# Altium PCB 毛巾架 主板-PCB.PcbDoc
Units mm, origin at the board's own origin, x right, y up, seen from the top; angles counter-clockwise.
Board outline 72 x 43 mm, 2 copper layers (Top Layer, Bottom Layer); 69 components, 52 nets, 212 pads, 98 vias.
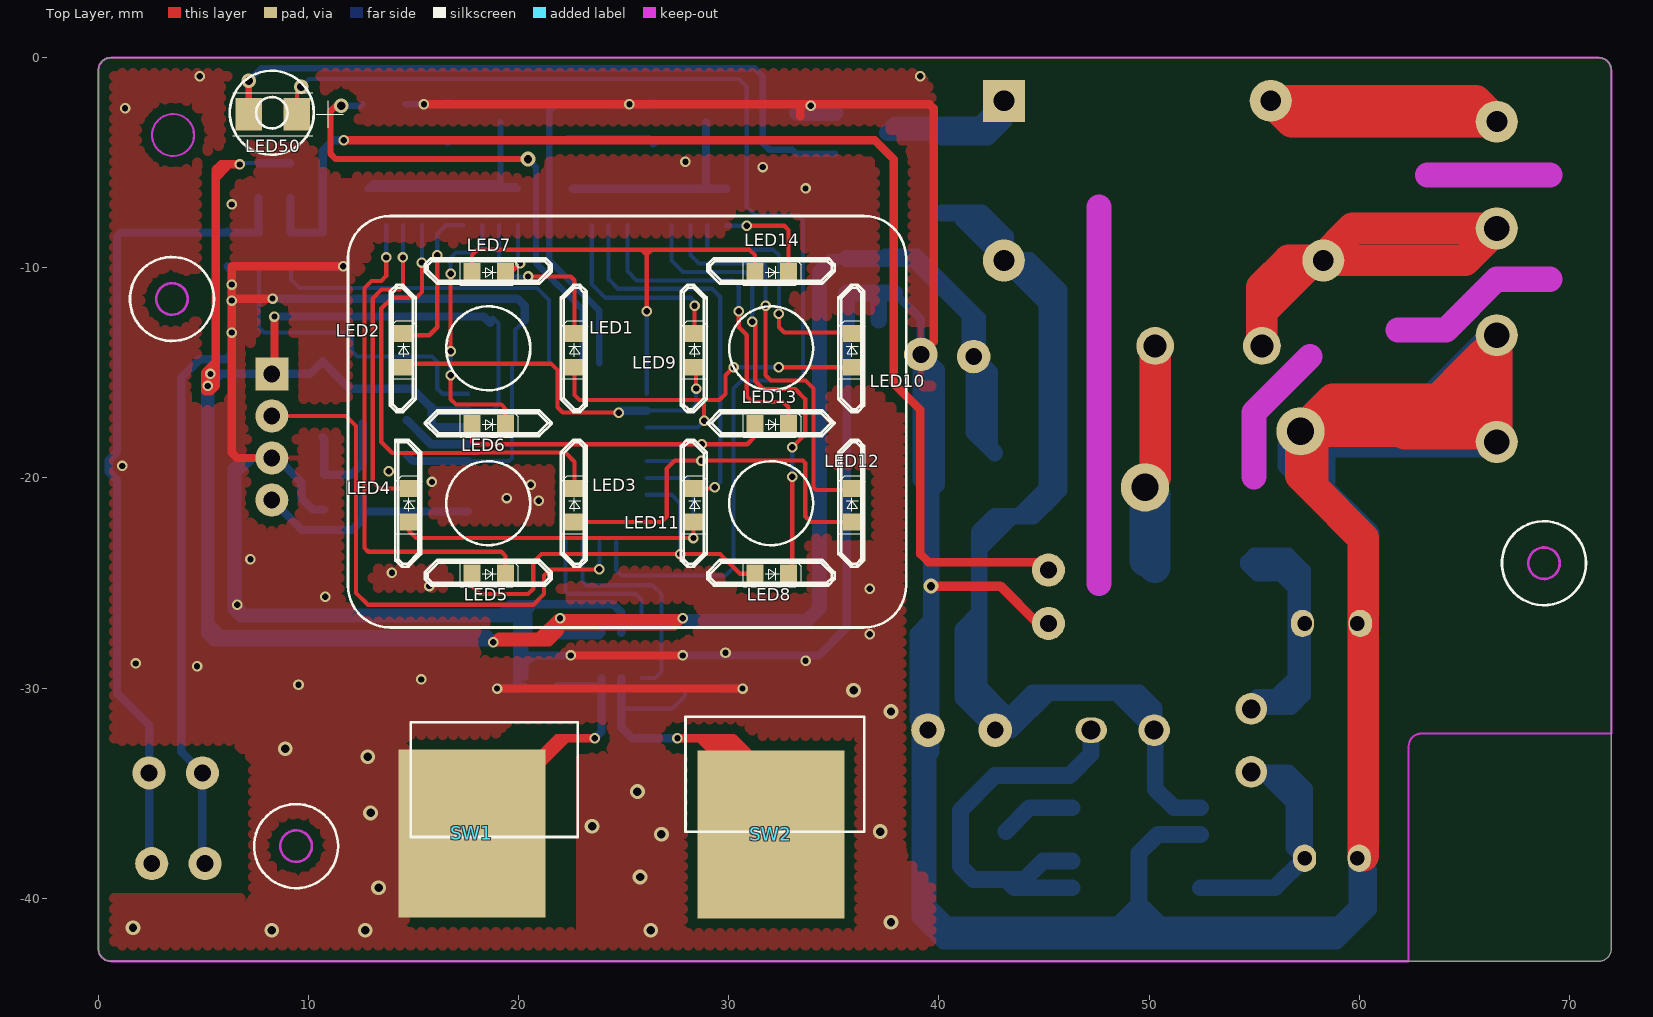
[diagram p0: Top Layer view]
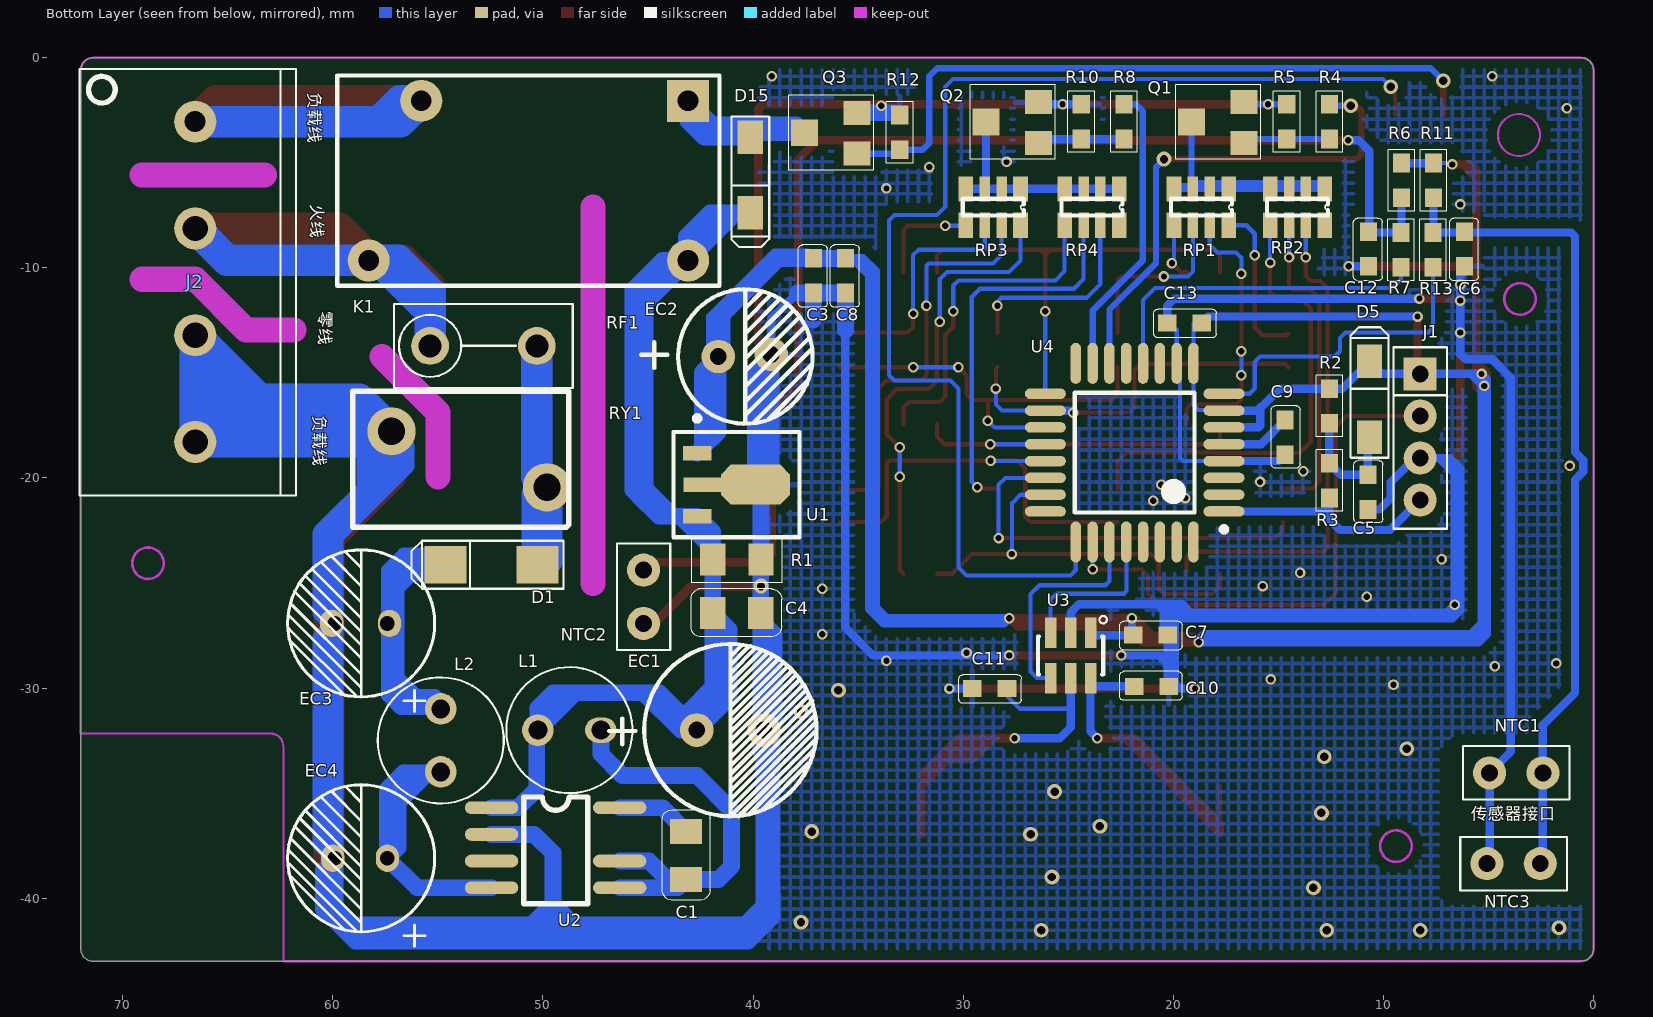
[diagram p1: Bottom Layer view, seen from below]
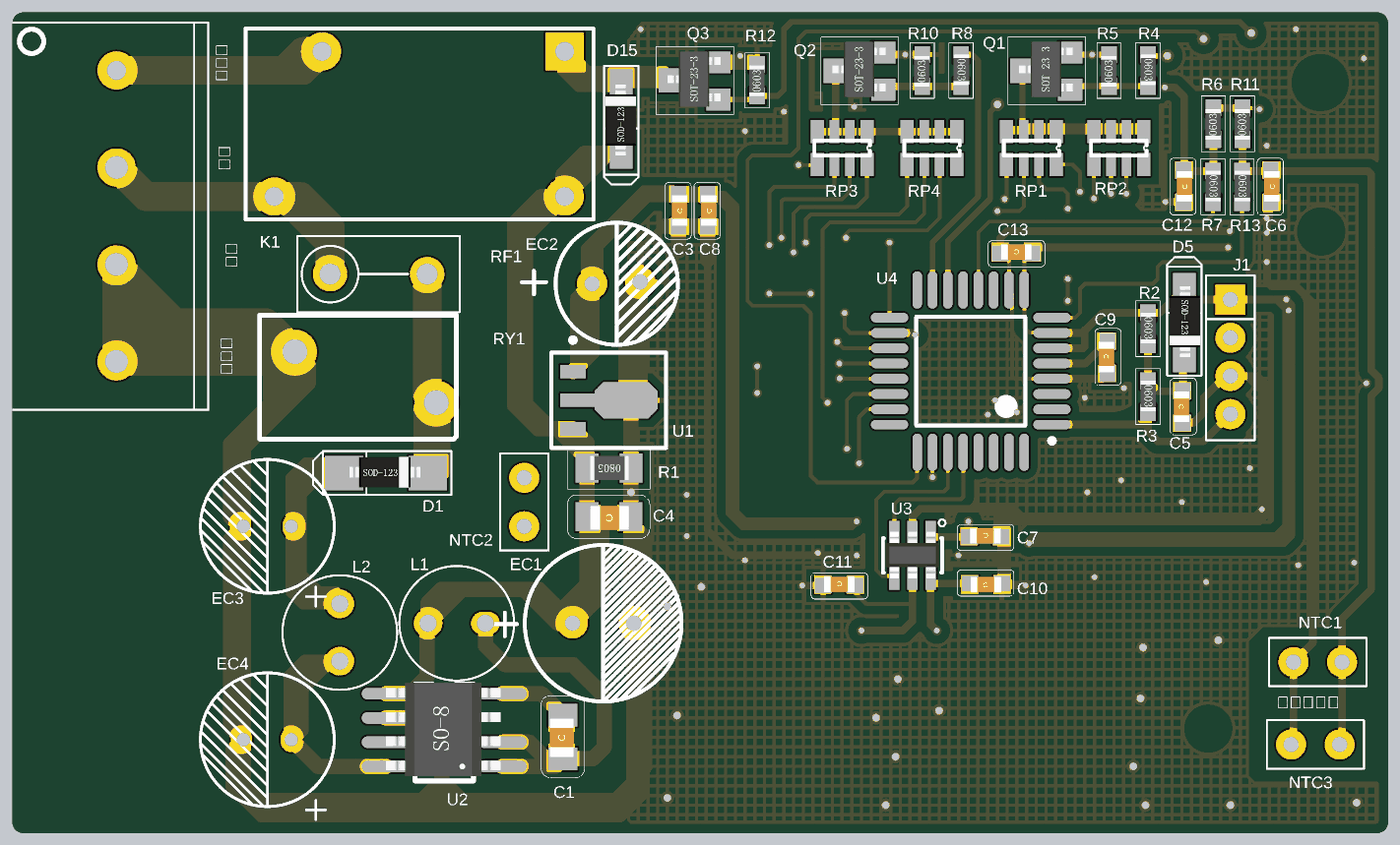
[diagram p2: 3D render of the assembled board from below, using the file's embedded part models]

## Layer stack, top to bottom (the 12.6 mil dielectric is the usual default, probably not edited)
Top Layer: signal copper 0.0356
Dielectric: dielectric 0.32, FR-4, Dk 4.8
Bottom Layer: signal copper 0.0356

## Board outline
0,-42.4 0,-0.6 cw(c0.6,-0.6) 0.6,0 71.4,0 cw(c71.4,-0.6) 72,-0.6 72,-42.4 cw(c71.4,-42.4) 71.4,-43 0.6,-43 cw(c0.6,-42.4)

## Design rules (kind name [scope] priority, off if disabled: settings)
Clearance Clearance_1 [InPolygon] p1: gap=0.45
Clearance [All] p2: gap=0.2
HoleSize [All] p1 off: absolutevalues=TRUE maxlimit=2.54 minlimit=0.025 maxpercent=80.000 minpercent=20.000
HoleToHoleClearance [All] p1 off: gap=0.254 allowstackedmicrovias=TRUE
LayerPairs [All] p1 off: enforce=TRUE
MinimumSolderMaskSliver [All] p1 off: minsoldermaskwidth=0.254
NetAntennae [All] p1 off: netantennaetolerance=0
PolygonConnect PolygonConnect_1 [IsVia] p1: connectstyle=Direct reliefconductorwidth=0.254 reliefentries=4 polygonreliefangle="90 Angle"
PolygonConnect [All] p2: connectstyle=Relief reliefconductorwidth=0.254 reliefentries=4 polygonreliefangle="90 Angle"
RoutingVias [All] p1: holewidth=0.711 width=1.27 viastyle="Through Hole" minholewidth=0.711 minwidth=1.27 maxholewidth=0.711 maxwidth=1.27
SilkToSilkClearance [All] p1 off: silktosilkclearance=0.254
SilkscreenOverComponentPads [All] p1 off: minsilkscreentomaskgap=0.254
SolderMaskExpansion [All] p1: expansion=0.102
Width [All] p1: maxlimit=1.5 minlimit=0.17 preferedwidth=0.4
21 further rules are at their usual default settings.

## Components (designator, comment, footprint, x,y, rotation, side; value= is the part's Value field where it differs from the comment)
C1 "1uF/0805" CAP/SMT/0805C 43.18,-39.116 r90 bottom
C3 "0.1uF/0603" CAP/SMT/0603C 37.084,-11.176 r90 bottom
C4 "1uF/0805" CAP/SMT/0805C 39.624,-26.416 r0 bottom
C5 "0.1uF/0603" CAP/SMT/0603C 10.795,-19.876 r270 bottom
C6 "0.1uF/0603" CAP/SMT/0603C 6.096,-9.906 r90 bottom
C7 "1uF/0603" CAP/SMT/0603C 20.289,-27.432 r0 bottom
C8 "0.1uF/0603" CAP/SMT/0603C 35.56,-11.176 r90 bottom
C9 "0.1uF/0603" CAP/SMT/0603C 14.732,-17.272 r270 bottom
C10 "0.1uF/0603" CAP/SMT/0603C 21.844,-29.972 r180 bottom
C11 "0.1uF/0603" CAP/SMT/0603C 27.94,-29.972 r0 bottom
C12 "0.1uF/0603" CAP/SMT/0603C 10.668,-9.906 r90 bottom
C13 "0.1uF/0603" CAP/SMT/0603C 18.669,-12.573 r0 bottom
D1 "1N4007-SOD123" D/SMT/SOD123 54.864,-24.13 r180 bottom
D5 "1N4148/SOD-123" D/SMT/SOD-123 10.668,-16.256 r270 bottom
D15 "1N4148/SOD-123" D/SMT/SOD-123 40.132,-5.588 r90 bottom
EC1 "AEC/220uF/25V" CAP/DIP/330UF/25V 42.672,-32.004 r180 bottom
EC2 "100uF/25V" CAP/DIP/100uF/25V 41.656,-14.224 r180 bottom
EC3 "2.2uF/400V" CAP/DIP/2.2UF/400V/2.5mm#1 57.404,-26.924 r90 bottom
EC4 "2.2uF/400V" CAP/DIP/2.2UF/400V/2.5mm#2 57.404,-38.1 r90 bottom
J1 "CON/DIP/1X4PIN/2MM" CON/DIP/1×4PIN/2.0MM 8.255,-15.05 r270 bottom
J2 "1X4PIN" CON/DIP/1×4PIN/5.08MM 66.548,-3.048 r270 bottom
K1 "HF32F/012-HSL" RELAY/HF32F-012-HSL 58.293,-9.652 r90 bottom
L1 "1mH" L/DIP/1mH#1 47.244,-32.004 r0 bottom
L2 "1mH" L/DIP/1mH#2 54.864,-30.988 r270 bottom
LED1 "WEJT61RC-871/0603" D/SMT/LED/0603 22.606,-13.207 r270 top
LED2 "WEJT61RC-871/0603" D/SMT/LED/0603 14.478,-13.207 r270 top
LED3 "WEJT61RC-871/0603" D/SMT/LED/0603 22.606,-20.573 r270 top
LED4 "WEJT61RC-871/0603" D/SMT/LED/0603 14.732,-20.573 r270 top
LED5 "WEJT61RC-871/0603" D/SMT/LED/0603 19.304,-24.511 r180 top
LED6 "WEJT61RC-871/0603" D/SMT/LED/0603 19.304,-17.399 r180 top
LED7 "WEJT61RC-871/0603" D/SMT/LED/0603 19.304,-10.16 r180 top
LED8 "WEJT61RC-871/0603" D/SMT/LED/0603 32.766,-24.511 r180 top
LED9 "WEJT61RC-871/0603" D/SMT/LED/0603 28.321,-13.207 r270 top
LED10 "WEJT61RC-871/0603" D/SMT/LED/0603 35.814,-13.207 r270 top
LED11 "WEJT61RC-871/0603" D/SMT/LED/0603 28.321,-20.573 r270 top
LED12 "WEJT61RC-871/0603" D/SMT/LED/0603 35.814,-20.573 r270 top
LED13 "WEJT61RC-871/0603" D/SMT/LED/0603 32.766,-17.399 r180 top
LED14 "WEJT61RC-871/0603" D/SMT/LED/0603 32.766,-10.16 r180 top
LED50 "4.7K/0603" D/SMT/LED/0805 7.112,-2.54 r0 top (schematic designator R9)
NTC1 "10K/±1%/B值:3380K/0805" Sensor/S_NTC_DIP 2.413,-34.036 r0 bottom
NTC2 "10K/±1%/B值:3380K/0805" Sensor/S_NTC_DIP 45.212,-24.384 r270 bottom
NTC3 "10K/±1%/B值:3380K/0805" Sensor/S_NTC_DIP 2.54,-38.354 r0 bottom (schematic designator NTC1)
Q1 "NPN_SS8050" BJT/SMT/SOT-23 16.637,-4.064 r90 bottom
Q2 "NPN_SS8050" BJT/SMT/SOT-23 26.416,-4.064 r90 bottom
Q3 "NPN_SS8050" BJT/SMT/SOT-23 35.052,-4.572 r90 bottom
R1 "4.7K//1%/0805" 0805R 39.624,-23.876 r0 bottom
R2 "10K/0603" 0603R 12.573,-16.574 r270 bottom
R3 "430R/0603" 0603R 12.573,-20.13 r270 bottom
R4 "10K/0603" 0603R 12.573,-3.048 r270 bottom
R5 "10K/0603" 0603R 14.605,-3.048 r90 bottom
R6 "10K/0603" 0603R 9.144,-5.842 r90 bottom
R7 "430R/0603" 0603R 9.167,-9.144 r270 bottom
R8 "10K/0603" 0603R 22.352,-3.048 r270 bottom
R10 "10K/0603" 0603R 24.384,-3.048 r90 bottom
R11 "10K/0603" 0603R 7.62,-5.842 r90 bottom
R12 "4.7K/0603" 0603R 33.02,-3.556 r90 bottom
R13 "430R/0603" 0603R 7.643,-9.144 r270 bottom
RF1 "100R/2W" FUSE/3.15A 50.292,-13.716 r0 bottom
RP1 "1K/0603/1/8W/±5%" 0603R*4 18.669,-7.112 r0 bottom
RP2 "1K/0603/1/8W/±5%" 0603R*4 14.097,-7.112 r0 bottom
RP3 "1K/0603/1/8W/±5%" 0603R*4 28.575,-7.112 r0 bottom
RP4 "1K/0603/1/8W/±5%" 0603R*4 23.876,-7.112 r0 bottom
RY1 "TDK471KD10" RES/RY/TDK471KD10 57.912,-17.78 r180 bottom
SW1 "TOUCH" SWITCH/TOUCH-2#1 17.907,-34.163 r90 top
SW2 "TOUCH" SWITCH/TOUCH-2#2 32.131,-33.909 r90 top
U1 "L78L05" SOT-89-3L(78L05) 42.672,-18.796 r270 bottom
U2 "PN8507" SOP-7 49.784,-38.1 r180 bottom
U3 "BS812" SOT23-6 24.892,-28.448 r180 bottom
U4 "STM8S005K6T6TR" LQFP32 21.844,-18.796 r0 bottom locked

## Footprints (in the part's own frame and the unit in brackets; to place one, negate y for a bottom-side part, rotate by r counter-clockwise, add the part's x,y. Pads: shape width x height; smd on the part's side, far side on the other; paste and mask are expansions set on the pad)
0603R [mil]
  rect 35x32 smd: 1(-32.5,0) 2(32.5,0)
  silkscreen extent -58,-25 58,25, body extent -33,-15 30,16, height 18
0603R*4 [mm]
  rect 0.7x1.2 smd: 1(-1.3,-0.865) 4(1.3,-0.865) 5(1.3,0.865) 8(-1.3,0.865)
  rect 0.5x1.2 smd: 2(-0.4,-0.865) 3(0.4,-0.865) 6(0.4,0.865) 7(-0.4,0.865)
  silkscreen extent -1.45,-0.4 1.45,0.4
0805R [mm]
  rect 1.2x1.524 smd: 1(0,0) 2(2.3,0)
  silkscreen extent -1,-1.1 3.3,1.1, body extent 0.13,-0.64 2.13,0.62, height 0.55
BJT/SMT/SOT-23 [mm] "transistor 1base 2emitter 3collector"
  rect 1.143x1.27 smd: 1(0,0) 2(1.95,0)
  rect 1.27x1.27 smd: 3(1,2.5)
  silkscreen extent -0.78,-0.8 2.78,3.26, body extent -0.38,-0.13 2.52,2.67, height 1.2
CAP/DIP/2.2UF/400V/2.5mm#1 [mm] "R=4.1MM  脚间距:3.2mm"
  oval 1.3x1.1 hole 0.7 copper offset 0,-0.1: 1(0,0)
  oval 1.3x1.1 hole 0.7 copper offset 0,0.15: 2(0,2.5)
  silkscreen extent -4.19,-2.25 3.5,4.75
CAP/DIP/2.2UF/400V/2.5mm#2 [mm] "R=4.1MM  脚间距:3.2mm"
  oval 1.3x1.1 hole 0.7: 1(0,0)
  oval 1.3x1.1 hole 0.7 copper offset 0,0.1: 2(0,2.5)
  silkscreen extent -4.19,-2.25 3.5,4.75
CAP/DIP/100uF/25V [mm]
  round 1.6 hole 0.8: 1(0,0) 2(2.515,0.102)
  silkscreen extent -3.68,-3.19 4.49,3.2
CAP/DIP/330UF/25V [mm] "R=4.1MM  脚间距:3.2mm"
  round 1.6 hole 0.8: 1(-0.009,0.004) 2(3.191,0.004)
  silkscreen extent -4.19,-4.1 5.69,4.1
CAP/SMT/0603C [mil]
  rect 35x32 smd: 1(-1,1.97) 2(64,1.97)
  silkscreen extent -28,-24 89,30, body extent -20,-20 82,19, height 35
CAP/SMT/0805C [mm]
  rect 1.2x1.524 smd: 1(0.01,0.01) 2(2.296,0.01)
  silkscreen extent -0.99,-1.13 3.32,1.15, body extent -0.38,-0.64 2.62,0.76, height 0.93
CON/DIP/1×4PIN/2.0MM [mil]
  rect 62x62 hole 31.5 mask+4: 1(0,0)
  round 62 hole 31.5 mask+4: 2(78.74,0) 3(157.48,0) 4(236.22,0)
  silkscreen extent -50,-50 290,50
CON/DIP/1×4PIN/5.08MM [mm]
  round 2 hole 1: 1(0,0)
  round 2 hole 1.2: 2(5.08,0) 3(10.16,0) 4(15.24,0)
  silkscreen extent -2.5,-5.5 17.78,4.8
D/SMT/LED/0603 [mm]
  rect 0.8x0.9 smd: 1(-0.076,0.051) 2(1.524,0.051)
  silkscreen extent -0.68,-0.55 2.07,0.68
D/SMT/LED/0805 [mil]
  rect 50x60 smd: 1(2,-6) 2(92,-6)
  silkscreen extent -28,-46 178,34
D/SMT/SOD123 [mm]
  rect 2x1.8 smd: 1(0.229,0) 2(4.597,0)
  silkscreen extent -1.4,-1.14 5.84,1.14, body extent 0.51,-0.76 4.21,0.84, height 1.2
D/SMT/SOD-123 [mm]
  rect 1.6x1.2 smd: 1(-1.8,0) 2(1.8,0)
  silkscreen extent -3.43,-0.9 2.78,0.9, body extent -1.91,-0.76 1.79,0.84, height 1.2
FUSE/3.15A [mm]
  round 1.8 hole 1.1: 1(0,0) 2(5.08,0)
  silkscreen extent -1.71,-2 6.79,2
L/DIP/1mH#1 [mm]
  oval 1.5x1.2 hole 0.9: 1(0,0)
  round 1.5 hole 0.9: 2(3,0)
  silkscreen extent -1.5,-3 4.5,3
L/DIP/1mH#2 [mm]
  round 1.5 hole 0.9: 1(0,0) 2(3,0)
  silkscreen extent -1.5,-3 4.5,3
LQFP32 [mm]
  oval 1.95x0.5 smd: 1(-4.25,2.8) 2(-4.25,2) 3(-4.25,1.2) 4(-4.25,0.4) 5(-4.25,-0.4) 6(-4.25,-1.2) 7(-4.25,-2) 8(-4.25,-2.8) 17(4.25,-2.8) 18(4.25,-2) 19(4.25,-1.2) 20(4.25,-0.4) 21(4.25,0.4) 22(4.25,1.2) 23(4.25,2) 24(4.25,2.8)
  oval 0.5x1.95 smd: 9(-2.8,-4.25) 10(-2,-4.25) 11(-1.2,-4.25) 12(-0.4,-4.25) 13(0.4,-4.25) 14(1.2,-4.25) 15(2,-4.25) 16(2.8,-4.25) 25(2.8,4.25) 26(2,4.25) 27(1.2,4.25) 28(0.4,4.25) 29(-0.4,4.25) 30(-1.2,4.25) 31(-2,4.25) 32(-2.8,4.25)
  silkscreen extent -4.37,-2.85 2.85,3.77
RELAY/HF32F-012-HSL [mm] "L×W×H（20.5*7.2*15.3MM）"
  round 2 hole 0.991: 1(7.6,-2.5) 2(0,0) 3(0,-15.2)
  rect 2x2 hole 0.991: 4(7.6,-15.2)
  silkscreen extent -1.2,-16.7 8.8,1.5
RES/RY/TDK471KD10 [mm]
  round 2.3 hole 1.3: 1(0.7,0) 2(8.1,-2.667)
  silkscreen extent -1.14,-4.57 9.14,1.91
Sensor/S_NTC_DIP [mil] "插件NTC封装 脚间距2.54mm"
  round 62 hole 31.5 mask+4: 1(0,0) 2(100,0)
  silkscreen extent -50,-50 150,50
SOP-7 [mil]
  oval 100x24 smd: 1(-104.73,94.83) 2(-104.73,44.83) 3(-104.73,-5.17) 4(-104.73,-55.17) 5(135.27,-55.17) 6(135.27,-5.17) 7(135.27,94.83)
  silkscreen extent -45,-85 75,115, body extent -105,-75 131,118, height 67
SOT23-6 [mm] "SOT-23/SC-74A; 5 Leads; Body 3.1 x 3 mm, inc. leads (LxW max)"
  rect 0.55x1.45 smd: 1(0.95,1.075) 2(0,1.075) 3(-0.95,1.075) 4(-0.95,-1.075) 5(0,-1.075) 6(0.95,-1.075)
  silkscreen extent -1.55,-0.9 1.72,1.88, body extent -1.4,-1.19 1.4,1.23, height 1.08
SOT-89-3L(78L05) [mm] "SOT-89; Body 4.6 x 4.25 mm, inc. leads (LxW max)"
  rect 0.7x1.35 smd: 1(0.024,0.009) 3(3.024,0.009)
  rect 0.7x1.8 smd: 2(1.524,0.254)
  oct 1.9x3.3 smd: 2(1.524,2.785)
  silkscreen extent -1.75,-1.12 4.02,4.88
SWITCH/TOUCH-2#1 [mm]
  rect 8x7 smd: 1(-2.754,0.127)
  silkscreen extent -2.92,-4.9 2.54,3.05
SWITCH/TOUCH-2#2 [mm]
  rect 8x7 smd: 1(-3.054,0.127)
  silkscreen extent -2.92,-4.32 2.54,4.19

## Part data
C1 C4: library part CAP/CAP/SMT/0805C
C3 C5 C6 C7 C8 C9 C10 C11 C12 C13: library part CAP/CAP/SMT/0603C
D1: library part D/D/SMT/1N4007-SOD123
D5 D15: library part D/D/SMT/1N4148/SOD-123, "VR=75V T(-65-175)P(0.5W)VF=0.6V"
EC1: library part CAP/AEC/DIP/330uF/25V
EC2: library part CAP/AEC/DIP/100uF/25V
EC3 EC4: library part CAP/AEC/DIP/2.2uF/400V
J1: "Connector"
J2: library part CON/DIP/1X4PIN/5.08MM, "Connector"
K1: library part RELAY/GENERAL/DIP/HF32F/012-HSL
L1 L2: library part L/L/DIP/JYGX68-1.0mH/300mA, "工字电感"
LED1 LED2 LED3 LED4 LED5 LED6 LED7 LED8 LED9 LED10 LED11 LED12 LED13 LED14: library part D/LED/SMT/WEJT61RC-871/0603
LED50 R2 R3 R4 R5 R6 R7 R8 R10 R11 R12 R13: library part RES/RES/SMT/0603
NTC1 NTC2 NTC3: library part SENSOR/NTC_SMD, "3380(10K)"
Q1 Q2: library part BJT/NPN/SMT/SS8050/SOT-23, "Vce25V/Vcb40V/Veb5V/Ic1.5V/Pd300mW"
Q3: library part BJT/NPN/SMT/SS8050/SOT-23
R1: library part RES/RES/SMT/0805
RF1: library part FUSE/FUSE/DIP/3.15A
RP1 RP2 RP3 RP4: library part "RES /PACKS/SMT/0603*4", "Isolated Resistor Network"
RY1: library part RES/RY/DIP/TDK471KD10
SW1 SW2: library part SWITCH/TOUCH
U1: library part IC/POWER/SMT/L78L05/SOT-89, "5V三端稳压器 output imax 0.1A"
U2: library part IC/POWER/SMT/PN8507/SOP-8
U3: library part IC/POWER/SMT/BS812
U4: library part MCU/SMT/STM8S005K6T6TR/LQFP32

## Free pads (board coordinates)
  round 0.1 on Mech10: 1(2.556,-3.62) 1(4.556,-3.62)

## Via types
v1: diameter 0.5, hole 0.3, Top Layer to Bottom Layer, tented both sides, 77 vias
v2: diameter 0.7, hole 0.4, Top Layer to Bottom Layer, tented both sides, 21 vias

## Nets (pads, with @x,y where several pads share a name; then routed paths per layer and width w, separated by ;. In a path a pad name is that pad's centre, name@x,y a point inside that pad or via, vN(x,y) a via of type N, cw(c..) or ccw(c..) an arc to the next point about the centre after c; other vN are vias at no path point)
+5V: C3.2 C7.2 C8.2 C13.1 D5.1 EC2.1 J1.1 R2.1 R6.2 R11.2 U1.1 U3.1 U4.6 U4.7 U4.9 | length 221.1
  Top Layer w0.4: v1@5.319,-15.05 5.207,-15.162 v1(5.207,-15.621) 5.588,-15.24 ; 5.588,-14.478 5.08,-14.986 5.08,-15.875 ; 5.588,-5.715 6.096,-5.207 6.096,-5.08 ; v1(6.731,-5.08) 6.096,-5.08 ; J1.1 8.382,-14.923 v1(8.382,-12.319) ; 21.082,-27.813 21.971,-26.924 ; 21.971,-27.051 27.432,-27.051 v1(27.813,-26.67) 22.479,-26.67 ; 5.08,-15.875 5.08,-15.304 v1(5.334,-15.05) 5.334,-15.875 ; 5.08,-15.875 5.334,-15.875 ; 5.334,-15.875 5.588,-15.621 5.588,-5.334 5.842,-5.08 6.096,-5.08 ; 21.971,-26.924 v1(21.971,-26.67) 22.479,-26.67 ; 21.971,-26.924 21.971,-27.305 21.463,-27.813 v1(18.796,-27.813) 19.05,-27.559 20.955,-27.559 21.844,-26.67 22.479,-26.67
  Bottom Layer w0.2: v1(6.731,-5.08) 6.794,-5.016 R11.2 ; U4.7 17.562,-16.764 18.796,-16.764 19.044,-16.516 U4.9 19.044,-12.642 C13.1@18.771,-12.369
  Bottom Layer w0.4: 5.334,-26.924 5.842,-27.432 18.542,-27.432 18.796,-27.686 v1(18.796,-27.813) 5.461,-27.813 5.08,-27.432 5.08,-15.304 v1(5.334,-15.05) ; v1@5.334,-15.558 5.842,-15.05 ; 5.842,-27.813 5.334,-27.305 v1(5.334,-15.05) ; R11.2 R6.2 ; v1(8.382,-12.319) 18.34,-12.319 C13.1 ; 15.875,-16.637 15.875,-16.701 ; U4.6 15.945,-17.596 15.875,-17.526 15.875,-16.891 ; U4.7 15.97,-16.796 ; v1(21.971,-26.67) 21.971,-27.426 C7.2 23.833,-27.482 U3.1 ; 35.179,-9.55 35.179,-9.652 34.48,-10.351 ; v1(5.334,-15.05) 5.842,-15.05 ; 5.842,-15.05 J1.1 10.074,-15.05 D5.1 11.961,-15.749 R2.1 14.923,-15.749 15.875,-16.701 ; 15.875,-16.891 15.875,-16.701 ; 15.875,-16.891 15.97,-16.796 ; 15.875,-16.701 15.97,-16.796 ; 34.163,-10.668 34.48,-10.351 ; 34.163,-10.668 34.163,-10.16 34.773,-9.55 C8.2 C3.2 ; 34.163,-10.668 34.163,-26.162 33.655,-26.67 v1(27.813,-26.67) 28.067,-26.924 33.782,-26.924 34.48,-26.226 34.48,-10.351 ; C3.2 37.413,-9.271 38.989,-9.271 42.037,-12.319 42.037,-12.7 ; C3.2 37.592,-9.55 ; 37.592,-9.55 37.792,-9.75 38.706,-9.75 38.862,-9.906 ; 37.592,-9.55 38.887,-9.55 42.037,-12.7 ; 37.592,-9.55 38.506,-9.55 38.862,-9.906 ; 38.862,-9.906 41.275,-12.319 ; 41.275,-12.319 41.275,-13.843 EC2.1 ; 41.275,-12.319 41.656,-12.7 EC2.1 ; EC2.1 42.037,-13.843 42.037,-12.7
  Bottom Layer w0.8: C8.2 38.506,-9.55 ; U1.1 U1.1@42.401,-18.559 ; U1.1@42.401,-18.559 42.401,-14.969 EC2.1 41.656,-17.814 U1.1@42.401,-18.559
+12V: C4.2 D15.1 EC1.1 K1.3 L1.2 R1.2 U1.3 U2.1 | length 94.2
  Bottom Layer w0.8: D15.1 41.148,-7.388 ; 41.656,-7.388 43.093,-8.825 K1.3 ; R1.2@41.924,-23.368 43.472,-21.82 43.839,-21.82 ; 42.291,-31.115 41.788,-31.115 41.144,-30.471 ; 45.085,-21.209 45.72,-20.574 45.72,-19.558 ; 45.148,-11.707 K1.3 ; 45.148,-11.049 43.751,-9.652 K1.3 ; 45.466,-20.828 44.474,-21.82 U1.3 ; 45.847,-30.226 45.212,-30.226 43.438,-32 EC1.1 ; U2.1 51.185,-35.691 50.292,-34.798 50.292,-32.052 L1.2 ; 41.144,-30.471 41.144,-27.202 C4.2 ; 41.144,-30.471 41.92,-29.695 41.92,-29.083 ; 41.148,-7.388 42.059,-7.388 43.18,-8.509 43.18,-9.565 K1.3 ; 41.148,-7.388 41.148,-7.707 K1.3 ; 41.92,-29.083 C4.2 ; 41.92,-29.083 41.92,-31.239 EC1.1 ; 41.92,-29.083 41.92,-29.982 43.053,-31.115 43.053,-31.628 EC1.1 ; C4.2 41.924,-26.422 R1.2 41.924,-22.559 U1.3 ; U1.3 43.839,-21.82 ; EC1.1 44.455,-30.226 48.514,-30.226 ; K1.3 44.323,-9.652 ; 43.839,-21.82 45.148,-20.511 ; 44.323,-9.652 45.72,-11.049 45.72,-19.558 ; 44.323,-9.652 45.148,-10.477 45.148,-20.511 ; 45.148,-20.511 45.72,-19.939 45.72,-19.558 ; 48.514,-30.226 49.53,-30.226 50.244,-30.94 L1.2 ; 48.514,-30.226 48.514,-30.274 L1.2
ADINSIDE: R7.2 U4.12 | length 16.5
  Bottom Layer w0.2: R7.2@9.167,-10.183 R7.2 9.167,-10.564 9.567,-10.964 20.87,-10.964 21.444,-11.538 U4.12
ADOUTSIDE: R13.2 U4.8 | length 15.2
  Bottom Layer w0.2: R13.2 7.643,-12.85 7.874,-13.081 11.811,-13.081 12.065,-13.335 12.065,-13.97 12.319,-14.224 15.875,-14.224 16.129,-14.478 16.129,-15.494 16.129,-15.742 16.383,-15.996 U4.8
COM1: R4.1 U4.14 | length 23.9
  Top Layer w0.3: v2(11.557,-2.286) 11.303,-2.286 11.049,-2.54 11.049,-4.572 11.303,-4.826 v2(20.447,-4.826)
  Bottom Layer w0.3: v2(11.557,-2.286) 12.509,-2.286 R4.1 ; v2@20.511,-4.889 20.828,-5.207 20.828,-9.779 23.044,-11.995 U4.14
COM2: R8.1 U4.15 | length 14
  Bottom Layer w0.3: R8.1 21.78,-2.222 21.463,-2.54 21.463,-9.652 23.844,-12.033 U4.15
GND: C3.1 C4.1 C5.2 C6.1 C7.1 C8.1 C9.2 C10.2 C11.2 C12.1 C13.2 EC1.2 EC2.2 EC3.2 EC4.2 J1.3 J2.3 J2.4 NTC1.2 NTC2.2 NTC3.2 Q1.2 Q2.2 Q3.2 R1.1 R5.2 R10.2 R12.2 RY1.1 U1.2 U2.2 U3.2 U4.4 U4.10 | length 528.7
  Top Layer w0.2: v1@15.43,-2.159 v1(15.494,-2.222)
  Top Layer w0.4: J1.3 6.604,-19.05 6.35,-18.796 v1(6.35,-11.557) ; v1(8.289,-11.464) 6.443,-11.464 v1(6.35,-11.557) ; v1(11.659,-9.931) 6.35,-9.931 v1(6.35,-11.557) ; v1(15.494,-2.222) v1(25.273,-2.222) 33.337,-2.222 ; v1(18.973,-30.022) v1(30.657,-30.022) ; v1(22.479,-28.448) v1(27.813,-28.448) ; 33.401,-2.794 33.401,-2.286 33.337,-2.222 ; EC2.2 39.751,-13.513 39.751,-2.413 39.56,-2.222 33.337,-2.222
  Top Layer w0.45: v2(39.624,-25.146) 42.926,-25.146 44.704,-26.924 NTC2.2
  Top Layer w1.5: RY1.1@57.785,-17.207 57.785,-20.447 ; EC4.2@60.198,-37.973 60.198,-22.86 57.785,-20.447 ; 62.164,-17.78 RY1.1 ; 62.164,-16.891 62.004,-16.731 ; 63.754,-16.256 65.341,-14.668 ; J2.4@65.659,-17.907 65.341,-17.59 ; J2.4 J2.3 66.548,-13.462 65.341,-14.668 ; J2.4@66.548,-17.907 62.164,-17.907 62.164,-16.256 ; 66.548,-16.256 62.164,-16.256 ; RY1.1 58.261,-16.731 ; RY1.1 57.212,-19.874 57.785,-20.447 ; 58.261,-16.731 62.004,-16.731 ; 58.261,-16.731 58.736,-16.256 62.164,-16.256 ; 62.004,-16.731 62.863,-17.59 65.341,-17.59 ; 65.341,-17.59 65.341,-14.668
  Bottom Layer w0.2: U4.4 19.539,-19.196 19.685,-19.05 19.685,-14.705 U4.10 19.844,-12.947 C13.2@20.295,-12.496 ; C13.2 C13.2@20.295,-12.496 ; C13.2@20.422,-12.369 C13.2@20.295,-12.496
  Bottom Layer w0.3: R5.2 v1(15.494,-2.222) 16.528,-2.222 Q1.2 ; Q2.2@26.307,-2.222 Q2.2
  Bottom Layer w0.4: NTC3.2 4.953,-38.227 NTC1.2 3.937,-33.02 3.937,-15.24 4.826,-14.351 6.096,-14.351 6.35,-14.097 v1(6.35,-10.795) 6.35,-10.135 C6.1 ; v1(8.289,-11.464) 19.939,-11.464 20.295,-11.82 C13.2@20.295,-12.496 ; C12.1 v1(11.659,-9.931) ; C5.2 10.199,-21.502 9.652,-20.955 9.652,-20.193 8.509,-19.05 J1.3 ; C9.2 14.98,-19.196 U4.4 ; v1(18.973,-30.022) 20.118,-30.022 C10.2 ; 19.177,-26.416 19.431,-26.162 ; 19.685,-30.022 19.939,-29.768 19.939,-26.67 19.685,-26.416 ; 20.264,-29.464 20.264,-28.448 ; 20.264,-28.885 20.701,-28.448 ; C7.1 20.264,-28.448 ; 20.499,-26.262 20.399,-26.162 19.431,-26.162 ; v1(22.479,-28.448) 20.701,-28.448 ; R10.2 v1(25.273,-2.222) Q2.2@26.307,-2.222 ; U3.2 24.892,-26.416 24.484,-26.008 20.753,-26.008 ; v1(27.813,-28.448) 34.29,-28.448 35.61,-27.128 C8.1 C3.1 37.897,-11.201 39.141,-12.446 EC2.2 ; C11.2 v1(30.657,-30.022) ; J1.3 7.366,-19.05 6.604,-19.812 v1(6.604,-26.035) 6.985,-26.416 19.685,-26.416 ; J1.3 6.858,-19.05 6.35,-19.558 6.35,-26.289 6.731,-26.67 20.091,-26.67 20.218,-26.797 20.218,-27.482 20.46,-27.241 20.46,-26.302 ; 19.431,-26.162 19.585,-26.008 20.753,-26.008 ; 19.685,-26.416 20.091,-26.416 20.218,-26.543 20.46,-26.302 ; 20.264,-28.448 20.701,-28.448 ; 20.46,-26.302 20.753,-26.008
  Bottom Layer w0.8: R12.2@33.274,-2.622 Q3.2 ; 35.61,-12.954 C8.1 37.897,-11.201 ; 37.134,-12.496 C3.1 ; 39.634,-33.03 39.634,-30.861 ; EC1.2@39.634,-32.161 38.996,-31.523 38.996,-27.425 39.634,-26.787 C4.1 ; EC1.2@39.634,-31.496 39.634,-30.861 ; 48.514,-41.275 49.276,-40.513 ; 49.53,-42.037 49.53,-40.513 ; 50.546,-41.275 49.784,-40.513 49.276,-40.513 ; U2.2 50.415,-36.961 49.53,-37.846 49.53,-40.513 ; 59.904,-40.386 59.015,-41.275 40.386,-41.275 39.481,-40.37 39.481,-40.259 ; EC3.2 60.579,-27.599 60.579,-37.425 EC4.2 ; EC3.2@60.198,-26.797 60.579,-26.416 60.579,-22.606 57.975,-20.002 ; 62.164,-17.653 62.037,-17.78 RY1.1 ; 39.481,-40.259 39.481,-41.282 40.236,-42.037 ; 39.481,-40.259 39.481,-37.592 39.481,-34.671 EC1.2 39.093,-32.388 39.093,-40.894 40.236,-42.037 ; U1.2@39.624,-20.584 R1.1 39.634,-23.886 C4.1 ; U1.2@39.624,-20.584 39.887,-20.32 39.887,-14.868 EC2.2 39.141,-20.101 U1.2@39.624,-20.584 ; 39.634,-30.861 C4.1 ; 40.236,-42.037 58.928,-42.037 59.182,-41.783 ; 49.276,-40.513 49.53,-40.513 ; 57.212,-20.128 RY1.1 ; 57.212,-20.128 56.515,-19.431 56.515,-18.477 RY1.1 ; 57.212,-20.128 59.904,-22.82 EC4.2 ; RY1.1 57.975,-18.544 57.975,-20.002 ; RY1.1 57.212,-19.239 57.975,-20.002 ; 59.182,-41.783 59.904,-41.061 EC4.2 ; 59.182,-41.783 60.452,-40.513 60.452,-38.648 EC4.2
  Bottom Layer w1.5: RY1.1 58.134,-16.858 ; 58.134,-20.161 58.134,-16.858 ; RY1.1@58.134,-17.78 58.642,-18.288 J2.4 ; 62.164,-16.256 62.164,-17.907 66.548,-17.907 J2.3 65.405,-14.351 ; 63.5,-16.256 65.405,-14.351 ; 65.151,-17.907 65.405,-17.653 ; 66.548,-16.256 58.736,-16.256 58.134,-16.858 ; 58.134,-16.858 61.75,-16.858 62.164,-17.272 62.545,-17.653 65.405,-17.653 ; 65.405,-17.653 65.405,-14.351
  other v1: 9.525,-29.845 15.367,-29.591 4.699,-28.956 1.778,-28.829 33.655,-28.702 29.845,-28.321 36.703,-27.432 10.795,-25.654 36.703,-25.273 15.748,-25.146 13.97,-24.511 7.239,-23.876 20.955,-21.082 19.431,-20.955 20.574,-20.32 15.875,-20.193 13.822,-19.685 1.143,-19.431 6.35,-13.081 6.35,-6.985 33.655,-6.223 31.623,-5.207 27.94,-4.953 1.27,-2.413 33.909,-2.286 4.826,-0.889 39.116,-0.889
  other v2: 8.255,-41.529 12.7,-41.529 26.289,-41.529 1.651,-41.402 37.719,-41.148 13.335,-39.497 25.781,-38.989 26.797,-36.957 37.211,-36.83 23.495,-36.576 12.954,-35.941 25.654,-34.925 12.827,-33.274 8.89,-32.893 37.719,-31.115 35.941,-30.099
L_LOAD: J2.1 K1.1 | length 35.9
  Top Layer w1.5: K1.1 65.552,-2.052 J2.1 56.789,-3.048 K1.1
  Bottom Layer w1.5: 57.785,-3.048 56.789,-2.052 K1.1 56.789,-3.048 J2.1
L_NINE: J2.2 K1.2 RF1.2 | length 46.8
  Top Layer w1.5: RF1.2 55.372,-12.065 ; 55.372,-12.065 55.372,-10.922 56.642,-9.652 65.024,-9.652 J2.2 59.69,-8.128 58.166,-9.652 57.785,-9.652 55.372,-12.065
  Bottom Layer w1.5: RF1.2 55.372,-11.176 56.896,-9.652 65.024,-9.652 J2.2 ; 55.372,-12.065 57.785,-9.652 K1.2
LED1: LED6.2 LED13.2 U4.20 | length 17.7
  Top Layer w0.2: LED6.2 17.78,-18.288 17.907,-18.415 17.926,-18.396 v1(28.721,-18.396) 30.88,-18.396 31.242,-18.034 LED13.2
  Bottom Layer w0.2: U4.20 v1(28.721,-18.396)
LED2: LED1.2 LED10.2 U4.19 | length 19.6
  Top Layer w0.2: LED1.2 22.657,-16.053 22.902,-16.298 28.829,-16.298 ; v1(28.829,-17.272) 28.829,-16.298 ; v1(30.226,-14.732) 29.845,-15.113 29.845,-16.002 29.549,-16.298 28.829,-16.298 ; v1(32.385,-14.732) v1(32.385,-14.732) LED10.2
  Bottom Layer w0.2: U4.19 28.505,-17.596 v1(28.829,-17.272) ; v1(30.226,-14.732) v1(32.385,-14.732)
LED3: LED7.2 LED14.2 U4.17 | length 22.9
  Top Layer w0.2: LED7.2 17.78,-9.398 18.034,-9.144 25.781,-9.144 ; v1@26.094,-11.938 26.094,-9.144 ; 26.416,-9.144 26.348,-9.144 26.094,-9.398 25.84,-9.144 25.781,-9.144 ; LED14.2 31.242,-9.398 30.988,-9.144 25.781,-9.144
  Bottom Layer w0.2: U4.17 v1(26.094,-12.065)
LED4: LED5.2 LED8.2 U4.23 | length 20.3
  Top Layer w0.2: LED5.2 17.78,-25.146 18.161,-25.527 20.447,-25.527 20.701,-25.273 20.701,-24.003 21.082,-23.622 v1(27.686,-23.622) 29.591,-23.622 30.531,-24.562 LED8.2
  Bottom Layer w0.2: U4.23 27.273,-20.796 27.686,-21.209 v1(27.686,-23.622)
LED5: LED3.2 LED12.2 U4.21 | length 21.1
  Top Layer w0.2: LED3.2 LED3.2 26.797,-22.098 27.051,-21.844 27.051,-19.558 27.432,-19.177 v1(28.702,-19.177) 33.528,-19.177 33.636,-19.285 33.636,-21.825 33.908,-22.097 LED12.2
  Bottom Layer w0.2: U4.21 v1@28.702,-19.196
LED6: LED4.2 LED11.2 U4.22 | length 19.8
  Top Layer w0.2: LED4.2 14.783,-22.53 15.113,-22.86 v1(28.321,-22.86) 28.321,-22.148 LED11.2
  Bottom Layer w0.2: U4.22 27.997,-19.996 28.321,-20.32 v1(28.321,-22.86)
LED7: LED2.2 LED9.2 U4.18 | length 17.6
  Top Layer w0.2: LED2.2 14.697,-14.563 17.272,-14.563 21.548,-14.563 21.844,-14.859 21.844,-16.637 22.098,-16.891 v1(24.765,-16.891) ; LED9.2 28.448,-14.807 28.448,-15.494
  Bottom Layer w0.2: U4.18 28.162,-16.796 28.448,-16.51 v1(28.448,-15.748)
  Bottom Layer w0.4: v1@24.797,-16.796 U4.18
NetC1_1: C1.1 L1.1 U2.5 U2.6 | length 20.4
  Bottom Layer w0.8: U2.5 43.585,-39.501 C1.1 ; U2.6 44.954,-38.231 44.079,-39.106 C1.1 ; L1.1 47.244,-33.147 46.228,-34.163 42.672,-34.163 41.021,-35.814 41.021,-38.481 41.646,-39.106 C1.1
NetC1_2: C1.2 U2.7 | length 3.6
  Bottom Layer w0.8: C1.2 44.319,-35.691 U2.7
NetC5_1: C5.1 D5.2 R2.2 R3.1 | length 5.8
  Bottom Layer w0.4: D5.2 10.745,-18.133 C5.1 12.027,-19.851 R3.1 R2.2
NetC6_2: C6.2 NTC1.1 NTC3.1 R11.1 R13.1 | length 39.4
  Bottom Layer w0.2: C6.2@6.146,-8.319 C6.2@6.184,-8.319 ; R13.1@7.62,-8.295 R13.1
  Bottom Layer w0.4: NTC3.1 2.413,-38.227 NTC1.1 2.413,-31.75 0.889,-30.226 0.889,-20.096 0.493,-19.7 0.493,-19.162 0.889,-18.766 0.889,-8.509 1.079,-8.319 C6.2@6.184,-8.319 ; C6.2 C6.2@6.184,-8.319 ; R13.1@7.62,-8.295 R11.1 ; R13.1 C6.2@6.184,-8.319
NetC9_1: C9.1 U4.5 | length 3.4
  Bottom Layer w0.4: C9.1 15.831,-18.396 U4.5
NetC10_1: C10.1 SW1.1 U3.6 | length 23.6
  Top Layer w0.2: SW1.1 SW1.1@17.78,-34.671
  Top Layer w0.4: SW1.1@20.828,-33.528 21.971,-32.385 21.844,-32.385 ; v1(23.622,-32.385) 22.479,-32.385 ; 21.844,-32.385 22.479,-32.385 ; 21.844,-32.385 17.78,-36.449 SW1.1 22.312,-32.385 22.479,-32.385
  Bottom Layer w0.4: C10.1 U3.6@23.892,-29.922 ; v1(23.622,-32.385) 23.942,-32.065 23.942,-29.922 U3.6
NetC11_1: C11.1 SW2.1 U3.5 | length 25.5
  Top Layer w0.4: v1(27.559,-32.385) 28.575,-32.385 ; SW2.1@30.353,-33.401 29.337,-32.385 ; SW2.1@31.242,-33.401 SW2.1@30.099,-33.401 ; SW2.1 32.004,-34.671 29.718,-32.385 ; SW2.1@32.004,-34.163 30.226,-32.385 29.718,-32.385 ; 28.575,-32.385 29.591,-33.401 SW2.1@30.099,-33.401 ; 28.575,-32.385 29.083,-32.385 ; 29.083,-32.385 29.337,-32.385 ; 29.083,-32.385 SW2.1@30.099,-33.401 ; 29.337,-32.385 29.718,-32.385
  Bottom Layer w0.2: 24.892,-30.988 27.305,-30.988 27.915,-30.378 C11.1
  Bottom Layer w0.4: U3.5 24.892,-30.988 24.892,-31.877 25.4,-32.385 v1(27.559,-32.385)
NetC12_2: C12.2 NTC2.1 R6.1 R7.1 | length 60.6
  Top Layer w0.4: v1(11.684,-3.937) 36.957,-3.937 37.846,-4.826 37.846,-15.494 39.116,-16.764 39.116,-23.622 39.497,-24.003 43.307,-24.003 44.831,-24.003 NTC2.1
  Bottom Layer w0.2: R7.1@9.144,-8.295 R7.1 ; C12.2@10.68,-8.319 C12.2
  Bottom Layer w0.4: R7.1@9.144,-8.295 R6.1 ; R7.1 10.68,-8.319 10.68,-4.433 11.176,-3.937 v1(11.684,-3.937)
NetD1_1: D1.1 EC3.1 L2.1 | length 33.3
  Bottom Layer w0.6: L2.1@55.118,-30.734 56.261,-30.734 56.896,-30.099 56.896,-27.559 ; 56.896,-29.464 56.007,-30.353 55.118,-30.353 54.864,-30.607 L2.1 56.769,-30.988 57.404,-30.353 EC3.1 ; 57.404,-29.464 57.404,-24.384 56.642,-23.622 54.991,-23.622 54.635,-23.978 D1.1 ; D1.1 56.388,-24.13 57.277,-25.019 EC3.1@57.277,-26.797 ; D1.1 55.143,-24.638 56.261,-24.638 56.896,-25.273 56.896,-27.559 ; 56.896,-27.559 56.896,-27.178 EC3.1@57.277,-26.797 ; EC3.1@57.277,-26.797 EC3.1 ; EC3.1@57.277,-26.797 EC3.1
NetD1_2: D1.2 RF1.1 RY1.2 | length 22.1
  Top Layer w1.5: RY1.2 50.292,-19.967 RF1.1
  Bottom Layer w1.5: D1.2@49.812,-23.929 RY1.2 ; D1.2@49.812,-23.802 50.267,-24.257 RY1.2@50.267,-20.775 ; RY1.2@50.267,-20.902 RY1.2 ; RF1.1 50.292,-19.967 RY1.2
NetD15_2: D15.2 K1.4 Q3.3 | length 15.1
  Bottom Layer w0.8: D15.2 41.357,-3.788 41.94,-3.205 ; D15.2 42.313,-3.788 43.093,-3.008 K1.4 41.94,-3.205 ; D15.2 39.916,-3.572 Q3.3 37.919,-3.205 41.94,-3.205
NetEC4_1: EC4.1 L2.2 U2.4 | length 17.2
  Bottom Layer w0.8: U2.4 56.003,-39.501 EC4.1 ; EC4.1 57.404,-34.798 56.642,-34.036 54.912,-34.036 L2.2 55.451,-33.988 56.896,-35.433 56.896,-37.592 EC4.1
NetLED1_1: LED1.1 RP1.6 | length 8.5
  Top Layer w0.2: v1(20.447,-10.414) 22.479,-10.414 22.657,-10.592 LED1.1
  Bottom Layer w0.2: RP1.6 19.069,-10.179 19.304,-10.414 v1(20.447,-10.414)
NetLED2_1: LED2.1 RP1.8 | length 7.6
  Top Layer w0.2: LED2.1 14.606,-13.208 15.748,-13.208 16.129,-12.827 v1(16.129,-9.398)
  Bottom Layer w0.2: v1(16.129,-9.398) 16.129,-8.382 16.534,-7.977 RP1.8
NetLED3_1: LED3.1 RP2.5 | length 22.7
  Top Layer w0.2: v1(15.397,-9.749) 15.397,-11.146 15.113,-11.43 13.97,-11.43 13.462,-11.938 13.462,-16.256 13.462,-18.288 13.989,-18.815 18.073,-18.815 18.092,-18.796 22.225,-18.796 22.657,-19.228 LED3.1
  Bottom Layer w0.2: v1(15.397,-9.749) RP2.5
NetLED4_1: LED4.1 RP2.6 | length 15.2
  Top Layer w0.2: v1(14.497,-9.506) 14.497,-10.884 14.351,-11.03 13.481,-11.03 13.062,-11.449 13.062,-20.174 13.385,-20.497 LED4.1
  Bottom Layer w0.2: v1(14.497,-9.506) RP2.6
NetLED5_1: LED5.1 RP2.7 | length 23.8
  Top Layer w0.2: v1(13.697,-9.506) 13.697,-10.395 13.462,-10.63 12.992,-10.63 12.662,-10.96 12.662,-23.33 12.846,-23.514 19.177,-23.514 19.38,-23.717 LED5.1
  Bottom Layer w0.2: v1(13.697,-9.506) RP2.7
NetLED6_1: LED6.1 RP1.7 | length 13.7
  Top Layer w0.2: v1(16.764,-15.113) 16.764,-16.256 17.018,-16.51 19.177,-16.51 19.38,-16.713 LED6.1 LED6.1@19.38,-17.221 ; v1(16.764,-13.97) v1(16.764,-10.287)
  Bottom Layer w0.2: v1(16.764,-15.113) v1(16.764,-13.97) ; v1(16.764,-10.287) 16.764,-9.525 17.018,-9.271 17.907,-9.271 18.269,-8.909 RP1.7 RP1.7@18.269,-8.528
NetLED7_1: LED7.1 RP1.5 | length 2.8
  Top Layer w0.2: LED7.1@19.507,-10.211 LED7.1 19.634,-10.211 v1(20.066,-9.779)
  Bottom Layer w0.2: v1@19.969,-9.779 RP1.5
NetLED8_1: LED8.1 RP3.8 | length 22.2
  Top Layer w0.2: v1(31.115,-12.573) 31.261,-12.719 31.261,-15.386 31.642,-15.767 33.166,-15.767 33.636,-16.237 33.636,-17.926 33.542,-18.02 33.542,-18.024 33.366,-18.2 33.362,-18.2 v1(33.02,-18.542) ; LED8.1 33.02,-24.384 v1(33.02,-19.939)
  Bottom Layer w0.2: RP3.8 27.275,-9.652 27.821,-10.198 30.772,-10.198 31.115,-10.541 v1(31.115,-12.573) ; v1(33.02,-19.939) v1(33.02,-18.542)
NetLED9_1: LED9.1 RP4.7 | length 9.6
  Top Layer w0.2: LED9.1 v1(28.372,-11.811)
  Bottom Layer w0.2: RP4.7 23.476,-10.776 24.13,-11.43 28.194,-11.43 28.372,-11.608 v1(28.372,-11.811)
NetLED10_1: LED10.1 RP3.6 | length 11.7
  Top Layer w0.2: v1(32.385,-12.192) 32.385,-12.827 32.638,-13.08 35.814,-13.08 LED10.1
  Bottom Layer w0.2: RP3.6 28.975,-9.036 29.083,-9.144 32.131,-9.144 32.385,-9.398 v1(32.385,-12.192)
NetLED11_1: LED11.1 RP4.6 | length 18.4
  Top Layer w0.2: LED11.1 29.287,-20.497 v1(29.337,-20.447)
  Bottom Layer w0.2: RP4.6 24.276,-10.541 24.733,-10.998 29.21,-10.998 29.591,-11.379 29.591,-20.193 v1(29.337,-20.447)
NetLED12_1: LED12.1 RP3.7 | length 19.7
  Top Layer w0.2: v1@31.75,-11.684 31.75,-13.97 31.75,-15.113 32.004,-15.367 33.655,-15.367 34.036,-15.748 34.036,-20.447 34.163,-20.574 35.788,-20.574 LED12.1
  Bottom Layer w0.2: RP3.7 28.175,-9.398 28.575,-9.798 31.642,-9.798 31.75,-9.906 v1(31.75,-11.811)
NetLED13_1: LED13.1 RP4.5 | length 16.2
  Top Layer w0.2: v1(30.48,-12.065) 30.48,-12.827 30.861,-13.208 30.861,-16.129 31.115,-16.383 32.588,-16.383 32.842,-16.637 LED13.1
  Bottom Layer w0.2: RP4.5 25.176,-10.16 25.614,-10.598 30.226,-10.598 30.48,-10.852 v1(30.48,-12.065)
NetLED14_1: LED14.1 RP3.5 | length 5.1
  Top Layer w0.2: v1(30.861,-8.001) 32.639,-8.001 32.842,-8.204 LED14.1
  Bottom Layer w0.2: RP3.5 29.899,-8.001 v1(30.861,-8.001)
NetQ1_1: Q1.1 R4.2 R5.1 | length 4.1
  Bottom Layer w0.3: R4.2 R5.1 16.447,-3.873 Q1.1
NetQ1_3: Q1.3 RP1.1 RP1.2 RP1.3 RP1.4 RP2.1 RP2.2 RP2.3 RP2.4 | length 19.6
  Bottom Layer w0.3: RP2.3 14.356,-6.106 12.938,-6.106 RP2.1 ; RP1.3 19.137,-6.179 Q1.3 ; RP2.1 13.075,-5.969 19.137,-5.969 19.274,-6.106 19.828,-6.106 RP1.4 14.097,-6.247 RP2.1
NetQ2_1: Q2.1 R8.2 R10.1 | length 4.1
  Bottom Layer w0.4: R8.2 R10.1 26.226,-3.873 Q2.1
NetQ2_3: Q2.3 RP3.1 RP3.2 RP3.3 RP3.4 RP4.1 RP4.2 RP4.3 RP4.4 | length 16.1
  Bottom Layer w0.3: RP4.2 RP4.3 RP4.4 RP3.1 RP3.2 RP3.3 ; Q2.3 Q2.3@28.975,-3.123
  Bottom Layer w0.4: RP4.1 RP4.2 RP4.3 RP4.4 RP3.1 RP3.2 RP3.3 ; Q2.3 28.916,-6.188 RP3.3 ; RP3.4 RP3.3
NetQ3_1: LED50.1 Q3.1 R12.1 | length 33.3
  Top Layer w0.3: LED50.1 v2(7.163,-1.092)
  Bottom Layer w0.3: v2(7.163,-1.092) 7.747,-0.508 31.242,-0.508 31.623,-0.889 31.623,-4.064 31.941,-4.381 R12.1 33.21,-4.572 Q3.1
RELAY1: LED50.2 U4.25 | length 58.2
  Top Layer w0.2: LED50.2 9.449,-1.6 v2(9.659,-1.39)
  Bottom Layer w0.2: v2(9.659,-1.39) 10.033,-1.016 30.48,-1.016 30.861,-1.397 30.861,-7.112 31.242,-7.493 33.274,-7.493 33.528,-7.747 33.528,-15.113 33.274,-15.367 30.607,-15.367 30.226,-15.748 30.226,-24.257 29.845,-24.638 24.892,-24.638 24.644,-24.39 U4.25
SW1: U3.3 U4.28 | length 7.2
  Bottom Layer w0.2: U4.28 22.225,-23.065 22.225,-25.381 22.352,-25.508 25.569,-25.508 25.842,-25.781 U3.3@25.842,-26.865
SW2: U3.4 U4.27 | length 10.6
  Bottom Layer w0.2: U4.27 23.044,-24.911 23.241,-25.108 26.378,-25.108 26.797,-25.527 26.797,-29.21 26.484,-29.523 U3.4
SWIM: J1.2 U4.26 | length 26.5
  Top Layer w0.2: J1.2 11.786,-17.05 12.262,-17.526 12.262,-25.47 12.827,-26.035 20.701,-26.035 21.209,-25.527 21.209,-24.638 21.495,-24.352 v1(23.844,-24.352)
  Bottom Layer w0.2: v1(23.844,-24.352) U4.26
TICERST: J1.4 R3.2 U4.1 | length 11.2
  Bottom Layer w0.4: J1.4 9.684,-22.479 12.065,-22.479 12.573,-21.971 R3.2 ; 12.573,-21.596 U4.1
pads on no net: RP2.8 RP4.8 U2.3 U4.2 U4.3 U4.11 U4.13 U4.16 U4.24 U4.29 U4.30 U4.31 U4.32

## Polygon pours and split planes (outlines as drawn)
GND on Bottom Layer "Top Layer-No Net" (hatched 90Degree grid 0.508 track 0.17, remove dead copper, pour order 1001): 0.6,-0.003 0,-0.794 0,-42.929 39.116,-43.003 39.751,-42.294 39.751,-1.509 38.608,-0.003
GND on Top Layer "Top Layer-No Net" (hatched 90Degree grid 0.508 track 0.508, remove dead copper, pour order 1000): 0.473,-0.057 -0.127,-0.853 -0.127,-42.983 38.989,-43.057 39.624,-42.475 39.624,-1.573 38.481,-0.057

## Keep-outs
Keep-Out Layer:
  circle w0.1: c3.556,-3.683 r1
  circle w0.127: c9.411,-37.52 r0.75
  circle w0.127: c3.506,-11.484 r0.75
  circle w0.127: c68.797,-24.058 r0.75
  lines w0.1: 0,-42.4 ccw(c0.6,-42.4) 0.6,-43 62.357,-43 62.357,-32.766 cw(c62.957,-32.766) 62.957,-32.166 72,-32.166 72,-0.6 ccw(c71.4,-0.6) 71.4,0 0.6,0 ccw(c0.6,-0.6) 0,-0.6 0,-42.4
  lines w1.2: 47.625,-25.019 47.625,-7.112 ; 54.991,-19.939 54.991,-16.891 57.658,-14.224 ; 61.849,-12.954 64.135,-12.954 66.548,-10.541 69.088,-10.541 ; 63.246,-5.588 69.088,-5.588

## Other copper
Top Layer:
  pour cut-out: 0.254,-32.512 6.477,-32.512 7.366,-33.401 7.366,-40.259 6.731,-40 0.376,-40 0,-39.624 0,-32.385
Bottom Layer:
  pour cut-out: 20.955,-12.192 20.955,-11.049 19.812,-9.906 13.335,-9.906 12.573,-10.668 12.573,-11.811 12.954,-12.192
  pour cut-out: 13.081,-1.27 19.939,-1.27 20.574,-1.905 20.574,-5.08 20.32,-5.334 12.039,-5.334 11.912,-5.461 11.912,-2.439
  pour cut-out: 38.227,-2.27 35.576,-2.27 34.925,-2.921 34.925,-3.683 35.433,-4.191 37.211,-4.191 37.211,-3.286
  pour cut-out: 38.735,-22.86 38.608,-22.987 38.608,-39.624 38.862,-40.005 38.862,-40 40.132,-40 40.005,-30.617 40.005,-22.733 39.116,-22.733 38.989,-22.86
  pour cut-out: 12.719,-15.894 14.116,-15.894 14.682,-16.46 14.682,-18.898 14.149,-19.431 12.954,-19.431 12.719,-19.196
  pour cut-out: 7.366,-12.7 7.366,-22.225 7.874,-22.733 9.779,-22.733 10.414,-22.098 10.414,-19.177 12.319,-17.272 12.319,-15.494 9.525,-12.7
  pour cut-out: -0.889,-32.131 6.604,-32.131 7.366,-32.893 7.366,-40.005 6.985,-40.386 0.386,-40.386 0,-40 0,-33.02

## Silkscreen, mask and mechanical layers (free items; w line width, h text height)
Top Overlay:
  drawing of 350 lines, arcs and shapes, not listed
Bottom Overlay:
  text "负载线" at 61.341,-1.651 h1 r90
  text "火线" at 61.214,-6.985 h1 r90
  text "零线" at 60.833,-12.065 h1 r90
  text "负载线" at 61.087,-17.018 h1 r90
  text "传感器接口" at 5.842,-36.449 h1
